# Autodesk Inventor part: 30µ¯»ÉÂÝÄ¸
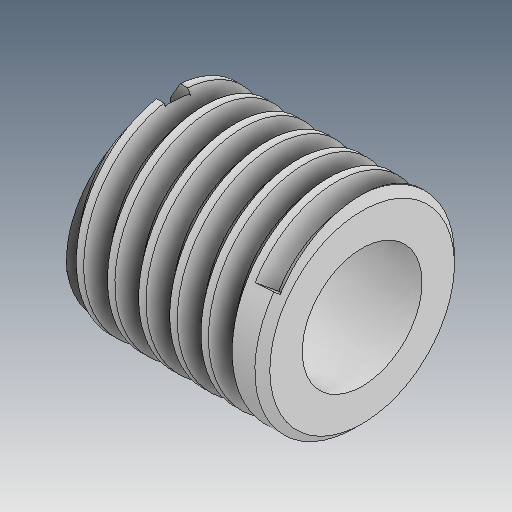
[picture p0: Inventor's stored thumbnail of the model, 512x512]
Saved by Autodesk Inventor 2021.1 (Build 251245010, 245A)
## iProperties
Created: 2019-05
Part Number: 30µ¯»ÉÂÝÄ¸
Material: Ogólny
Document SubType Name: Modeling
Designer: user
Density: 1 g/cm^3
Appearance: Domyślna
Author: user
Revision Number: ÈÎºÎ
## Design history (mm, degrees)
feature "ÊäÈë1"
node "Bryła1"
